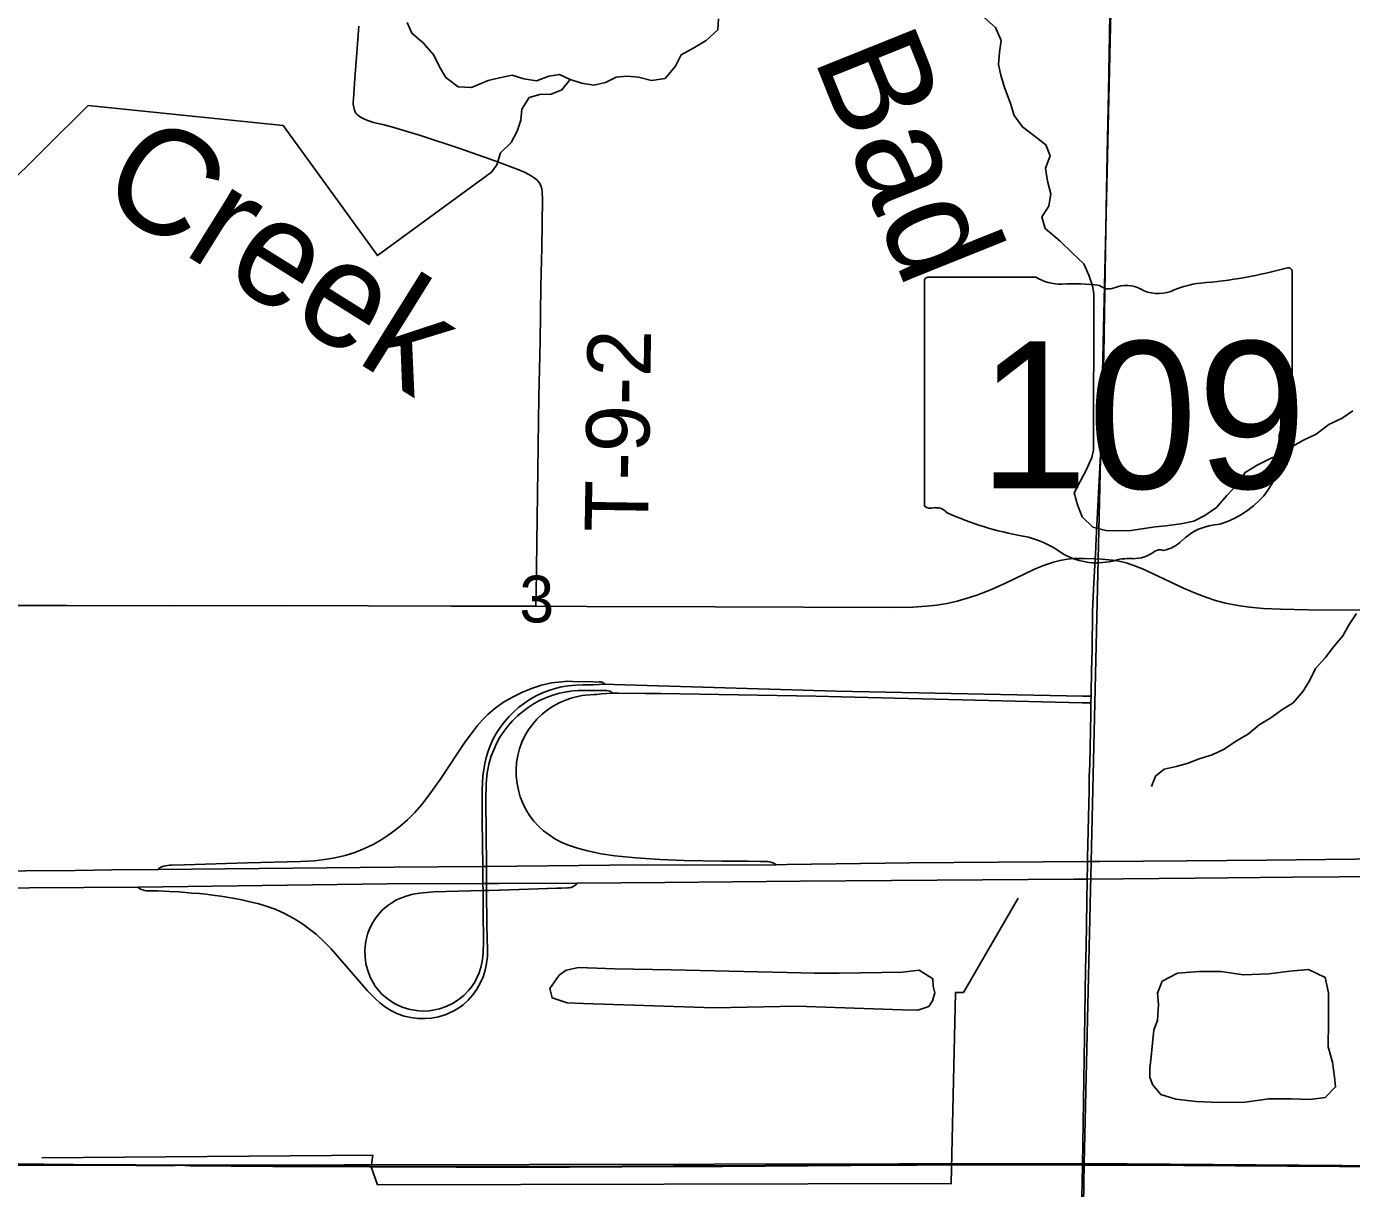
# Model space of a CAD drawing. Extents: x 0 to 42, y 0 to 22.
# Drawn here: x 3.302 to 4.49, y 18.47 to 19.512 of the extents above; entities that cross this region are included whole.
import ezdxf

# ---------------------------------------------------------------- set-up
doc = ezdxf.new("R2010")
doc.units = 0
for name, color, linetype in [('GM_X_County_Road', 7, 'Continuous'), ('GM_X_Interchange_Ramps', 7, 'Continuous'), ('GM_X_Interstate_Route', 7, 'Continuous'), ('GM_X_Minor_Lake', 7, 'Continuous'), ('GM_X_Minor_River', 7, 'Continuous'), ('GM_X_Minor_River_Text', 7, 'Continuous'), ('GM_X_Section', 7, 'Continuous'), ('GM_X_Section_Text', 7, 'Continuous'), ('GM_X_State_Location', 7, 'Continuous'), ('GM_X_State_Route', 7, 'Continuous'), ('GM_X_State_Shield', 7, 'Continuous'), ('GM_X_Township_Road', 7, 'Continuous'), ('GM_X_Township_Road_Text', 7, 'Continuous')]:
    doc.layers.add(name, color=color, linetype=linetype)

msp = doc.modelspace()

# ---------------------------------------------------------------- linework, layer by layer
at = {"layer": 'GM_X_County_Road'}
for points in [[(3.2517, 18.492), (3.2912, 18.4915), (3.344, 18.491), (3.4, 18.4905), (3.4309, 18.4904), (3.4394, 18.4908), (3.4481, 18.4904), (3.5598, 18.4895), (3.5939, 18.4897), (3.6094, 18.4894), (3.6871, 18.489), (3.7586, 18.4892), (3.789, 18.4892), (3.8823, 18.4897), (3.9258, 18.4896), (4.0408, 18.4905), (4.0999, 18.4908), (4.1372, 18.4912), (4.2485, 18.4908)], [(4.2485, 18.4908), (4.3392, 18.4905), (4.4791, 18.4896), (4.5475, 18.4893), (4.5745, 18.4891)]]:
    msp.add_lwpolyline(points, dxfattribs=at)
at = {"layer": 'GM_X_Interchange_Ramps'}
for points in [[(3.4015, 18.7401), (3.4021, 18.7395), (3.403, 18.7388), (3.4041, 18.7383), (3.4061, 18.7376), (3.4077, 18.7371), (3.409, 18.7369), (3.4199, 18.7367), (3.4299, 18.7363), (3.4386, 18.7358), (3.4498, 18.7348), (3.4568, 18.7343), (3.463, 18.7337), (3.4685, 18.733), (3.4759, 18.732), (3.4885, 18.73), (3.4949, 18.7288), (3.5009, 18.7273), (3.51, 18.7252), (3.5159, 18.7235), (3.5247, 18.7203), (3.5331, 18.7164), (3.5414, 18.712), (3.5493, 18.7071), (3.5568, 18.7016), (3.5617, 18.6977), (3.5685, 18.6914), (3.5749, 18.6847), (3.6076, 18.6472), (3.6141, 18.6405), (3.6187, 18.6363), (3.6237, 18.6326), (3.6289, 18.6293), (3.6345, 18.6267), (3.6404, 18.6246), (3.6464, 18.6232), (3.6526, 18.6224), (3.6588, 18.6223), (3.665, 18.6228), (3.6711, 18.6239), (3.6771, 18.6257), (3.68, 18.6268), (3.6856, 18.6295), (3.6908, 18.6328), (3.6933, 18.6347), (3.6978, 18.6389), (3.7019, 18.6436), (3.7055, 18.6487), (3.7086, 18.6541), (3.7111, 18.6598), (3.713, 18.6657), (3.7143, 18.6717), (3.715, 18.6779), (3.7152, 18.6841), (3.7144, 18.7059), (3.7142, 18.7371), (3.7142, 18.7434), (3.7141, 18.7588), (3.7137, 18.8177), (3.714, 18.8332), (3.7149, 18.8425), (3.7167, 18.8516), (3.7185, 18.8576), (3.7207, 18.8634), (3.7233, 18.869), (3.7263, 18.8745), (3.7297, 18.8797), (3.7334, 18.8846), (3.7375, 18.8893), (3.7419, 18.8936), (3.7467, 18.8976), (3.7517, 18.9013), (3.7569, 18.9047), (3.7623, 18.9077), (3.768, 18.9103), (3.7738, 18.9124), (3.7798, 18.9142), (3.7859, 18.9154), (3.792, 18.9163), (3.7966, 18.9165), (3.8016, 18.9166), (3.8117, 18.9166), (3.8201, 18.9164), (3.8221, 18.9164), (3.8236, 18.9162), (3.8247, 18.9159), (3.8258, 18.9155), (3.8264, 18.915), (3.827, 18.9142)], [(3.8205, 18.922), (3.8196, 18.9228), (3.8188, 18.9233), (3.8178, 18.9238), (3.8171, 18.924), (3.8161, 18.9241), (3.8151, 18.9241), (3.8131, 18.924), (3.81, 18.9242), (3.7916, 18.9246), (3.7868, 18.9247), (3.7818, 18.9243), (3.7724, 18.9232), (3.7634, 18.9212), (3.7546, 18.9183), (3.7459, 18.9147), (3.7376, 18.9106), (3.7296, 18.9061), (3.722, 18.9005), (3.7153, 18.8948), (3.7106, 18.8901), (3.7062, 18.8852), (3.7025, 18.8804), (3.6952, 18.8703), (3.6726, 18.8368), (3.6618, 18.8216), (3.6561, 18.8143), (3.6499, 18.8072), (3.6434, 18.8006), (3.6364, 18.7944), (3.6291, 18.7887), (3.6214, 18.7835), (3.6133, 18.7788), (3.6049, 18.7747), (3.5963, 18.7713), (3.5874, 18.7685), (3.5783, 18.7664), (3.5691, 18.7649), (3.5599, 18.7638), (3.5475, 18.763), (3.4999, 18.762), (3.4434, 18.7601), (3.4316, 18.7598), (3.43, 18.7598), (3.4282, 18.7596), (3.4264, 18.7594), (3.4246, 18.759), (3.4231, 18.7585), (3.4222, 18.7581), (3.4213, 18.7575), (3.4204, 18.7568), (3.4197, 18.7559)], [(4.2564, 18.9114), (4.2489, 18.9113), (4.0279, 18.916), (3.8582, 18.9208), (3.8283, 18.9218), (3.8205, 18.922), (3.8099, 18.9216), (3.801, 18.9214), (3.7943, 18.9211), (3.7879, 18.9206), (3.7815, 18.9196), (3.7758, 18.9182), (3.7701, 18.9166), (3.7644, 18.9143), (3.7588, 18.9117), (3.7534, 18.9086), (3.7482, 18.9052), (3.7433, 18.9014), (3.7386, 18.8973), (3.7342, 18.8929), (3.7301, 18.8882), (3.7264, 18.8833), (3.723, 18.878), (3.72, 18.8726), (3.7175, 18.8669), (3.7153, 18.8611), (3.7136, 18.8552), (3.7123, 18.8491), (3.7109, 18.8399), (3.7103, 18.8275), (3.7102, 18.7995), (3.7108, 18.7588), (3.711, 18.7434), (3.7111, 18.737), (3.7113, 18.7188), (3.7116, 18.6908), (3.7113, 18.6815), (3.7106, 18.6753), (3.7095, 18.6692), (3.7076, 18.6633), (3.7051, 18.6576), (3.7037, 18.6549), (3.7001, 18.6498), (3.6982, 18.6474), (3.6938, 18.643), (3.6889, 18.6392), (3.6836, 18.6359), (3.678, 18.6331), (3.6722, 18.6311), (3.6661, 18.6297), (3.663, 18.6293), (3.6568, 18.629), (3.6537, 18.6292), (3.6476, 18.63), (3.6446, 18.6307), (3.6386, 18.6326), (3.633, 18.6352), (3.6302, 18.6367), (3.6251, 18.6402), (3.6204, 18.6443), (3.6183, 18.6465), (3.6145, 18.6514), (3.6128, 18.654), (3.6099, 18.6595), (3.6077, 18.6653), (3.6061, 18.6713), (3.6053, 18.6775), (3.6051, 18.6837), (3.6056, 18.6899), (3.6062, 18.6929), (3.6078, 18.6989), (3.6089, 18.7018), (3.6117, 18.7074), (3.615, 18.7126), (3.619, 18.7175), (3.6211, 18.7197), (3.6258, 18.7238), (3.6283, 18.7256), (3.6336, 18.7288), (3.6364, 18.7301), (3.6423, 18.7322), (3.6483, 18.7338), (3.6544, 18.7348), (3.6668, 18.7359), (3.711, 18.737)], [(3.9741, 18.7602), (3.9729, 18.7611), (3.972, 18.7616), (3.9711, 18.762), (3.9701, 18.7623), (3.9692, 18.7625), (3.9679, 18.7627), (3.9662, 18.763), (3.9641, 18.7631), (3.9596, 18.7632), (3.9484, 18.7635), (3.9251, 18.7635), (3.8916, 18.7639), (3.8697, 18.7648), (3.848, 18.7664), (3.8293, 18.7683), (3.817, 18.7701), (3.8047, 18.7726), (3.7957, 18.775), (3.7868, 18.7781), (3.7811, 18.7806), (3.7756, 18.7836), (3.7704, 18.7869), (3.7654, 18.7906), (3.7608, 18.7948), (3.7566, 18.7994), (3.7528, 18.8044), (3.7495, 18.8097), (3.7467, 18.8153), (3.7445, 18.8211), (3.7428, 18.8271), (3.7416, 18.8332), (3.7409, 18.8395), (3.7408, 18.8457), (3.7412, 18.8519), (3.7422, 18.8581), (3.7438, 18.8641), (3.7458, 18.87), (3.7485, 18.8757), (3.7517, 18.881), (3.7554, 18.8861), (3.7595, 18.8908), (3.764, 18.8951), (3.7688, 18.899), (3.774, 18.9025), (3.7795, 18.9054), (3.7852, 18.9079), (3.7911, 18.9099), (3.7972, 18.9114), (3.8, 18.912), (3.8033, 18.9124), (3.8071, 18.9127), (3.8106, 18.9129), (3.8131, 18.913), (3.817, 18.9134), (3.827, 18.9142)], [(3.827, 18.9142), (3.8325, 18.9142), (3.8564, 18.9137), (3.8702, 18.9138), (4.0095, 18.9113)], [(4.0095, 18.9113), (4.0325, 18.9109), (4.2483, 18.9055), (4.2562, 18.9053)], [(3.7112, 18.737), (3.7142, 18.7371), (3.7165, 18.7372), (3.7257, 18.7375), (3.7265, 18.7375), (3.7773, 18.7391), (3.7814, 18.7392), (3.7869, 18.7394), (3.7881, 18.7395), (3.7896, 18.7397), (3.7903, 18.7399), (3.7914, 18.7403), (3.7924, 18.7409), (3.7933, 18.7415), (3.7943, 18.7423), (3.7955, 18.7437)], [(4.5473, 18.4899), (4.4789, 18.4901), (4.339, 18.491), (4.2482, 18.4914), (4.1369, 18.4917), (4.0996, 18.4914), (4.0406, 18.4911), (3.9255, 18.4902), (3.882, 18.4903), (3.7888, 18.4898), (3.7584, 18.4897), (3.6869, 18.4896), (3.6092, 18.49), (3.5937, 18.4903), (3.5596, 18.4901), (3.4479, 18.4909), (3.4392, 18.4913), (3.4306, 18.4909), (3.3998, 18.4911), (3.3438, 18.4915), (3.2909, 18.492)], [(3.2909, 18.492), (3.3438, 18.4915), (3.3998, 18.4911), (3.4306, 18.4909), (3.4392, 18.4913), (3.4479, 18.4909), (3.5596, 18.4901), (3.5937, 18.4903), (3.6092, 18.49), (3.6869, 18.4896), (3.7584, 18.4897), (3.7888, 18.4898), (3.882, 18.4903), (3.9255, 18.4902), (4.0406, 18.4911), (4.0996, 18.4914), (4.1369, 18.4917), (4.2482, 18.4914), (4.339, 18.491), (4.4789, 18.4901), (4.5473, 18.4899)]]:
    msp.add_lwpolyline(points, dxfattribs=at)
at = {"layer": 'GM_X_Interstate_Route'}
msp.add_line((3.7252, 18.7435), (3.7955, 18.7437), dxfattribs=at)
for points in [[(2.1, 18.7447), (2.1951, 18.7455), (2.2417, 18.7461), (2.248, 18.7461), (2.3909, 18.7474), (2.879, 18.7516), (2.9785, 18.7524), (3.2552, 18.7544), (3.2561, 18.7544), (3.3454, 18.7551), (3.3783, 18.7556), (3.4197, 18.7559), (3.6312, 18.758), (3.7108, 18.7588), (3.7141, 18.7588), (3.852, 18.7601), (3.8917, 18.7599), (3.9741, 18.7602)], [(3.9741, 18.7602), (3.9837, 18.7603), (4.0936, 18.7619), (4.253, 18.7631), (4.2646, 18.7632), (4.3423, 18.7638), (4.4138, 18.7644), (4.5195, 18.7654)], [(4.2408, 18.7473), (4.2528, 18.7474), (4.3498, 18.7482), (4.4369, 18.749), (4.5208, 18.7496)], [(2.1, 18.7298), (2.1168, 18.73), (2.2477, 18.7311), (2.2536, 18.7312), (2.3406, 18.7318), (2.5054, 18.7333), (2.5893, 18.734), (2.6733, 18.7346), (2.8039, 18.7354), (2.9624, 18.7368), (3.0681, 18.7376), (3.2474, 18.7391), (3.2558, 18.7391), (3.4015, 18.7401)], [(3.4015, 18.7401), (3.6251, 18.7431), (3.711, 18.7434), (3.7142, 18.7434), (3.7252, 18.7435)], [(3.7955, 18.7437), (3.8741, 18.7442), (3.9954, 18.7455), (4.2408, 18.7473)]]:
    msp.add_lwpolyline(points, dxfattribs=at)
at = {"layer": 'GM_X_Minor_Lake'}
for p, q in [((3.9837, 18.6636), (3.8798, 18.6659)), ((4.3126, 18.6122), (4.3101, 18.5879))]:
    msp.add_line(p, q, dxfattribs=at)
for points in [[(3.8798, 18.6659), (3.8294, 18.667), (3.7968, 18.6681), (3.7857, 18.6657), (3.7795, 18.6613), (3.7709, 18.6493), (3.773, 18.6409), (3.7865, 18.6365), (3.8013, 18.6357), (3.9185, 18.632), (3.9925, 18.6334), (4.0869, 18.6301), (4.1009, 18.6298), (4.1108, 18.633), (4.114, 18.6383), (4.1161, 18.6454), (4.1147, 18.6515), (4.1145, 18.658), (4.1021, 18.6658), (4.0873, 18.6639), (4.0687, 18.6636), (4.0303, 18.6629), (4.0083, 18.663), (3.9837, 18.6636)], [(4.3101, 18.5879), (4.3091, 18.5777), (4.3089, 18.5697), (4.3114, 18.5632), (4.3188, 18.5543), (4.3323, 18.5499), (4.3505, 18.5479), (4.371, 18.5471), (4.3945, 18.5473), (4.4158, 18.5503), (4.4356, 18.5502), (4.4526, 18.5498), (4.4663, 18.5514), (4.4756, 18.5611), (4.4747, 18.5702), (4.4728, 18.5832), (4.4689, 18.5969), (4.4691, 18.6197), (4.4693, 18.6455), (4.4662, 18.6592), (4.4512, 18.6664), (4.4345, 18.6649), (4.4158, 18.6623), (4.393, 18.6616), (4.373, 18.6644), (4.3533, 18.6644), (4.3339, 18.6629), (4.32, 18.6557), (4.316, 18.6451), (4.3169, 18.6349), (4.3158, 18.6205), (4.3126, 18.6122)]]:
    msp.add_lwpolyline(points, dxfattribs=at)
at = {"layer": 'GM_X_Minor_River'}
for points in [[(3.643, 19.5154), (3.6473, 19.5058), (3.6573, 19.4972), (3.6669, 19.486), (3.672, 19.4756), (3.6778, 19.466), (3.6887, 19.4578), (3.7008, 19.4572), (3.7157, 19.4633), (3.726, 19.4657), (3.7371, 19.4681), (3.7476, 19.4648), (3.759, 19.4631), (3.7701, 19.4674), (3.7796, 19.4687), (3.7893, 19.4643), (3.7995, 19.461), (3.8105, 19.4593), (3.8208, 19.4617), (3.8304, 19.4664), (3.8403, 19.4673), (3.8505, 19.4663), (3.8622, 19.4634), (3.8744, 19.4651), (3.8837, 19.4762), (3.8889, 19.4864), (3.9008, 19.4929), (3.9112, 19.4992), (3.9217, 19.5088), (3.9223, 19.5186)], [(4.1606, 19.5198), (4.1706, 19.5108), (4.1757, 19.4993), (4.1743, 19.4887), (4.1733, 19.4777), (4.1753, 19.4682), (4.1788, 19.4571), (4.1838, 19.4437), (4.1873, 19.4319), (4.1947, 19.4218), (4.2051, 19.414), (4.2159, 19.4058), (4.2195, 19.3958), (4.2155, 19.3849), (4.2171, 19.3731), (4.2202, 19.3617), (4.2184, 19.3507), (4.2121, 19.341), (4.2153, 19.3306), (4.2287, 19.3193), (4.2398, 19.3085), (4.2499, 19.2991), (4.2542, 19.2888), (4.2577, 19.2792), (4.2587, 19.2724)], [(3.7893, 19.4643), (3.7819, 19.455), (3.7723, 19.451), (3.7621, 19.4509), (3.7525, 19.448), (3.7458, 19.4376), (3.7449, 19.4277), (3.7416, 19.4179), (3.7364, 19.4078), (3.7267, 19.3985), (3.7234, 19.3879), (3.7187, 19.3812)], [(3.7187, 19.3812), (3.6164, 19.3064), (3.5319, 19.423), (3.357, 19.4409), (3.2797, 19.364), (3.2716, 19.3566), (3.262, 19.3546), (3.2522, 19.354), (3.2426, 19.3527)], [(4.2587, 19.2724), (4.2584, 19.1319)], [(4.2584, 19.1319), (4.2571, 19.1255), (4.2523, 19.1146), (4.2464, 19.1037), (4.2412, 19.0936), (4.244, 19.0829), (4.2483, 19.0722), (4.2579, 19.0628), (4.2696, 19.0599), (4.2806, 19.0597), (4.292, 19.0598), (4.3038, 19.0618), (4.3137, 19.0631), (4.3232, 19.064), (4.3369, 19.066), (4.3484, 19.0684), (4.3583, 19.0735), (4.3688, 19.0805), (4.3781, 19.0913), (4.3882, 19.1021), (4.3945, 19.1118), (4.4053, 19.1184), (4.4161, 19.1238), (4.4268, 19.1289), (4.4372, 19.1355), (4.4468, 19.141), (4.458, 19.1464), (4.4695, 19.1549), (4.4814, 19.1607), (4.4911, 19.1673)], [(4.4944, 18.9854), (4.4877, 18.9757), (4.4821, 18.9656), (4.474, 18.9559), (4.4661, 18.9458), (4.4576, 18.9361), (4.4524, 18.9256), (4.4465, 18.9159), (4.4375, 18.9055), (4.4275, 18.8992), (4.4174, 18.8919), (4.407, 18.8857), (4.3974, 18.8775), (4.3858, 18.8706), (4.3758, 18.864), (4.365, 18.8589), (4.3532, 18.8553), (4.3425, 18.851), (4.3325, 18.8482), (4.3219, 18.8458), (4.3141, 18.8396), (4.3105, 18.8305)], [(4.1908, 18.7302), (4.1419, 18.6456), (4.1347, 18.6458), (4.131, 18.4743), (3.6165, 18.4732), (3.6108, 18.4893), (3.6122, 18.4999), (3.3155, 18.4974)]]:
    msp.add_lwpolyline(points, dxfattribs=at)
at = {"layer": 'GM_X_Section'}
for points in [[(4.2741, 19.5242), (4.2501, 18.4923), (3.2549, 18.4906), (3.2701, 19.5386)], [(5.2524, 18.4847), (4.2501, 18.4923), (4.2741, 19.5242), (5.2739, 19.514)], [(3.2549, 18.4906), (4.2501, 18.4923), (4.2338, 17.4876), (3.2323, 17.4917)], [(4.2501, 18.4923), (5.2524, 18.4847), (5.2334, 17.4797), (4.2338, 17.4876)]]:
    msp.add_lwpolyline(points, close=True, dxfattribs=at)
at = {"layer": 'GM_X_State_Route'}
for points in [[(4.2602, 19.0384), (4.261, 19.0526), (4.2655, 19.1396), (4.2679, 19.2173), (4.2689, 19.2919), (4.2697, 19.3479), (4.2708, 19.3977), (4.2718, 19.453), (4.2749, 19.6272), (4.2757, 19.668), (4.2779, 19.7858), (4.2816, 20.0004), (4.2845, 20.1404), (4.2874, 20.2896)], [(4.2586, 19.0074), (4.26, 19.0344), (4.2602, 19.0384)], [(4.253, 18.7592), (4.253, 18.7631), (4.2531, 18.7664), (4.2546, 18.8269), (4.2547, 18.8397), (4.2551, 18.8501), (4.2561, 18.8954), (4.2562, 18.9053), (4.2564, 18.9114), (4.2563, 18.9135), (4.2567, 18.9348), (4.2573, 18.9524), (4.2576, 18.9874), (4.2586, 19.0074)], [(4.2485, 18.4908), (4.2507, 18.6249), (4.2514, 18.6669), (4.252, 18.6866), (4.2528, 18.7474), (4.253, 18.7592)], [(4.2444, 18.2416), (4.2457, 18.3238), (4.2478, 18.4479), (4.2485, 18.4908)]]:
    msp.add_lwpolyline(points, dxfattribs=at)
at = {"layer": 'GM_X_State_Shield'}
for p, q in [((4.107, 19.2836), (4.107, 19.0835)), ((4.2067, 19.2871), (4.1102, 19.2871)), ((4.4366, 19.1873), (4.4366, 19.292)), ((4.4365, 19.1874), (4.4366, 19.1873))]:
    msp.add_line(p, q, dxfattribs=at)
for centre, major_axis, start_param, end_param in [((4.3192, 19.5599), (0.3495, 0), 4.814394, 5.042369), ((4.4329, 19.2925), (0.00367, 0), 6.141152, 7.989035), ((4.1107, 19.284), (0.00382, 0), 1.712693, 3.28349), ((4.2297, 19.3103), (0.037, 0), 4.042523, 4.731795), ((4.242, 19.1747), (0.133, 0), 1.404758, 1.657858), ((4.2722, 19.2851), (0.0107, 0), 3.836095, 5.185415), ((4.2879, 19.2619), (0.0222, 0), 0.950623, 2.079405), ((4.3165, 19.2937), (0.0267, 0), 4.081561, 5.145723), ((4.3637, 19.2259), (0.0703, 0), 1.699011, 2.107814), ((4.4326, 19.1869), (0.00393, 0), 5.05454, 6.418171), ((4.4357, 19.1796), (0.00568, 0), 1.883978, 3.671073), ((4.3996, 19.1664), (0.0341, 0), 5.934695, 6.695948), ((4.4497, 19.1435), (0.0248, 0), 2.387724, 3.262537), ((4.3387, 19.1302), (0.0874, 0), 5.101752, 6.440018), ((4.1108, 19.0831), (0.00385, 0), 3.00124, 4.508301), ((4.1114, 19.1035), (0.0294, 0), 4.665946, 4.897461), ((4.1174, 19.0719), (0.0106, 0), 0.519207, 1.627899), ((4.2512, 19.2517), (0.2524, 0), 4.195997, 4.488961), ((4.3756, 19.0273), (0.0479, 0), 1.647645, 2.488434), ((4.176, 18.9936), (0.079, 0), 0.823519, 1.323587), ((4.3149, 19.0641), (0.0282, 0), 4.937069, 5.64225), ((4.2614, 19.071), (0.0501, 0), 4.026481, 4.996735), ((4.2903, 19.0018), (0.0412, 0), 1.495662, 1.94098), ((4.294, 19.056), (0.0267, 0), 4.691044, 5.507374), ((4.3181, 19.0366), (0.00752, 0), 1.147584, 2.315152)]:
    msp.add_ellipse(centre, major_axis=major_axis, ratio=0.8, start_param=start_param, end_param=end_param, dxfattribs=at)
at = {"layer": 'GM_X_Township_Road'}
for points in [[(3.7586, 18.992), (3.7588, 19.0022), (3.7593, 19.0489), (3.7613, 19.1796), (3.7623, 19.2294), (3.763, 19.2792), (3.7637, 19.3134), (3.7644, 19.3569), (3.7641, 19.3632), (3.7637, 19.3663), (3.7629, 19.3692), (3.7614, 19.3719), (3.7593, 19.3742), (3.7569, 19.3762), (3.7543, 19.378), (3.7517, 19.3795), (3.7489, 19.3809), (3.7432, 19.3834), (3.7227, 19.3909), (3.6904, 19.4023), (3.655, 19.4141), (3.6311, 19.4212), (3.6212, 19.4239), (3.613, 19.4258), (3.607, 19.4277), (3.6042, 19.4291), (3.6012, 19.4305), (3.5985, 19.4327), (3.5975, 19.4338), (3.5966, 19.4351), (3.5955, 19.4379), (3.5952, 19.4391), (3.5947, 19.4421), (3.5946, 19.4439), (3.5949, 19.447), (3.5963, 19.4656), (3.5977, 19.4842), (3.5998, 19.5122)], [(3.7586, 18.992), (3.8041, 18.9919), (3.9192, 18.9916), (4.0778, 18.9909), (4.0964, 18.9912), (4.1088, 18.9921), (4.118, 18.9931), (4.1272, 18.9946), (4.1362, 18.9966), (4.1452, 18.9991), (4.154, 19.002), (4.1655, 19.0065), (4.1797, 19.0128), (4.205, 19.0248), (4.2137, 19.0284), (4.2226, 19.0315), (4.2286, 19.0331), (4.2348, 19.0342), (4.2411, 19.0347), (4.2505, 19.0348), (4.26, 19.0344)], [(4.26, 19.0344), (4.2661, 19.0341), (4.2754, 19.0333), (4.2816, 19.0323), (4.2877, 19.0308), (4.2937, 19.0289), (4.3025, 19.0255), (4.3166, 19.0189), (4.3391, 19.0082), (4.3504, 19.0033), (4.3591, 19), (4.368, 18.9972), (4.3769, 18.9949), (4.386, 18.993), (4.3983, 18.9912), (4.4106, 18.9901), (4.4261, 18.9893), (4.451, 18.9888), (4.504, 18.9884)], [(3.2602, 18.9929), (3.2692, 18.9928), (3.3376, 18.9927), (3.434, 18.9925), (3.5335, 18.9927), (3.6828, 18.9922), (3.7586, 18.992)]]:
    msp.add_lwpolyline(points, dxfattribs=at)

# ---------------------------------------------------------------- texts
at = {"layer": 'GM_X_Minor_River_Text'}
for s, rotation, p in [('Bad', 291.8909, (4.007, 19.484)), ('Creek', 328.0165, (3.3629, 19.3575))]:
    msp.add_text(s, height=0.09476, rotation=rotation, dxfattribs=at).set_placement(p)
at = {"layer": 'GM_X_Section_Text'}
msp.add_text('3', height=0.0419, rotation=0, dxfattribs=at).set_placement((3.7437, 18.9775))
at = {"layer": 'GM_X_State_Location'}
for s in ['s', 'r']:
    msp.add_text(s, height=0.000189, dxfattribs=at).set_placement((4.2681, 19.1703))
msp.add_text('109', height=0.000189, rotation=0, dxfattribs=at).set_placement((4.2012, 19.1565))
at = {"layer": 'GM_X_State_Shield'}
msp.add_text('109', height=0.13184, dxfattribs=at).set_placement((4.1554, 19.0976))
at = {"layer": 'GM_X_Township_Road_Text'}
msp.add_text('T-9-2', height=0.05682, rotation=89.0959, dxfattribs=at).set_placement((3.859, 19.058))

doc.saveas('drawing.dxf')
